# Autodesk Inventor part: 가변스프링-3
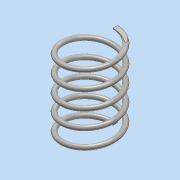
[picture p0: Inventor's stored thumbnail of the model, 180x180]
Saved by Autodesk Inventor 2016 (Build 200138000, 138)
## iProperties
Created: 2015-11
Part Number: 가변스프링-3
Material: 스테인레스 스틸
Document SubType Name: Modeling
Designer: Administrator
Density: 8 g/cm^3
Appearance: 반연마
Mass: 8.59389 g
Surface Area: 21.7235 cm^2
Volume: 1.07424 cm^3
Author: Administrator
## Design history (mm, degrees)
sketch "스케치2"
  geometry: L1 (0, 0)-(11, 0); L2 (11, 0)-(11, 36.561); L3 (11, 36.561)-(0, 36.561); L4 (0, 36.561)-(0, 0); C1 r 1 at (11, 0)
  constraints: 8 end point, 2 parallel, 1 centre point, 1 coincident, 1 horizontal, 1 perpendicular
  dimensions: "d0" = 2 diameter of C1; "d1" = 22 diameter of L2 L4; "d2" = 36.5612 distance between parallel lines of L3 L1 (derived)
feature "코일1" sketch "스케치2" pitch "d3" = 10; turns "d5" = 5; dims "d4" = 36.5612 (= d2), "d6" = 0, angle "d7" = 90 deg, angle "d8" = 90 deg, "d9" = 0, "d10" = 0
sketch "스케치3"
  geometry: L1 (0, 12)-(0, 10) reference; 1 further point
  constraints: 1 vertical alignment
extrude "돌출1" cut sketch "스케치3" distance "d11" = 10; taper "d12" = 0 deg
node "작업 평면1"
sketch "스케치4"
  geometry: L1 (0, -1)-(0, 1) reference; 1 further point
  constraints: 1 vertical alignment
extrude "돌출2" cut sketch "스케치4" distance "d13" = 10; taper "d14" = 0 deg
node "솔리드1"
node "절단 모서리 투영1"
node "절단 모서리 투영2"
